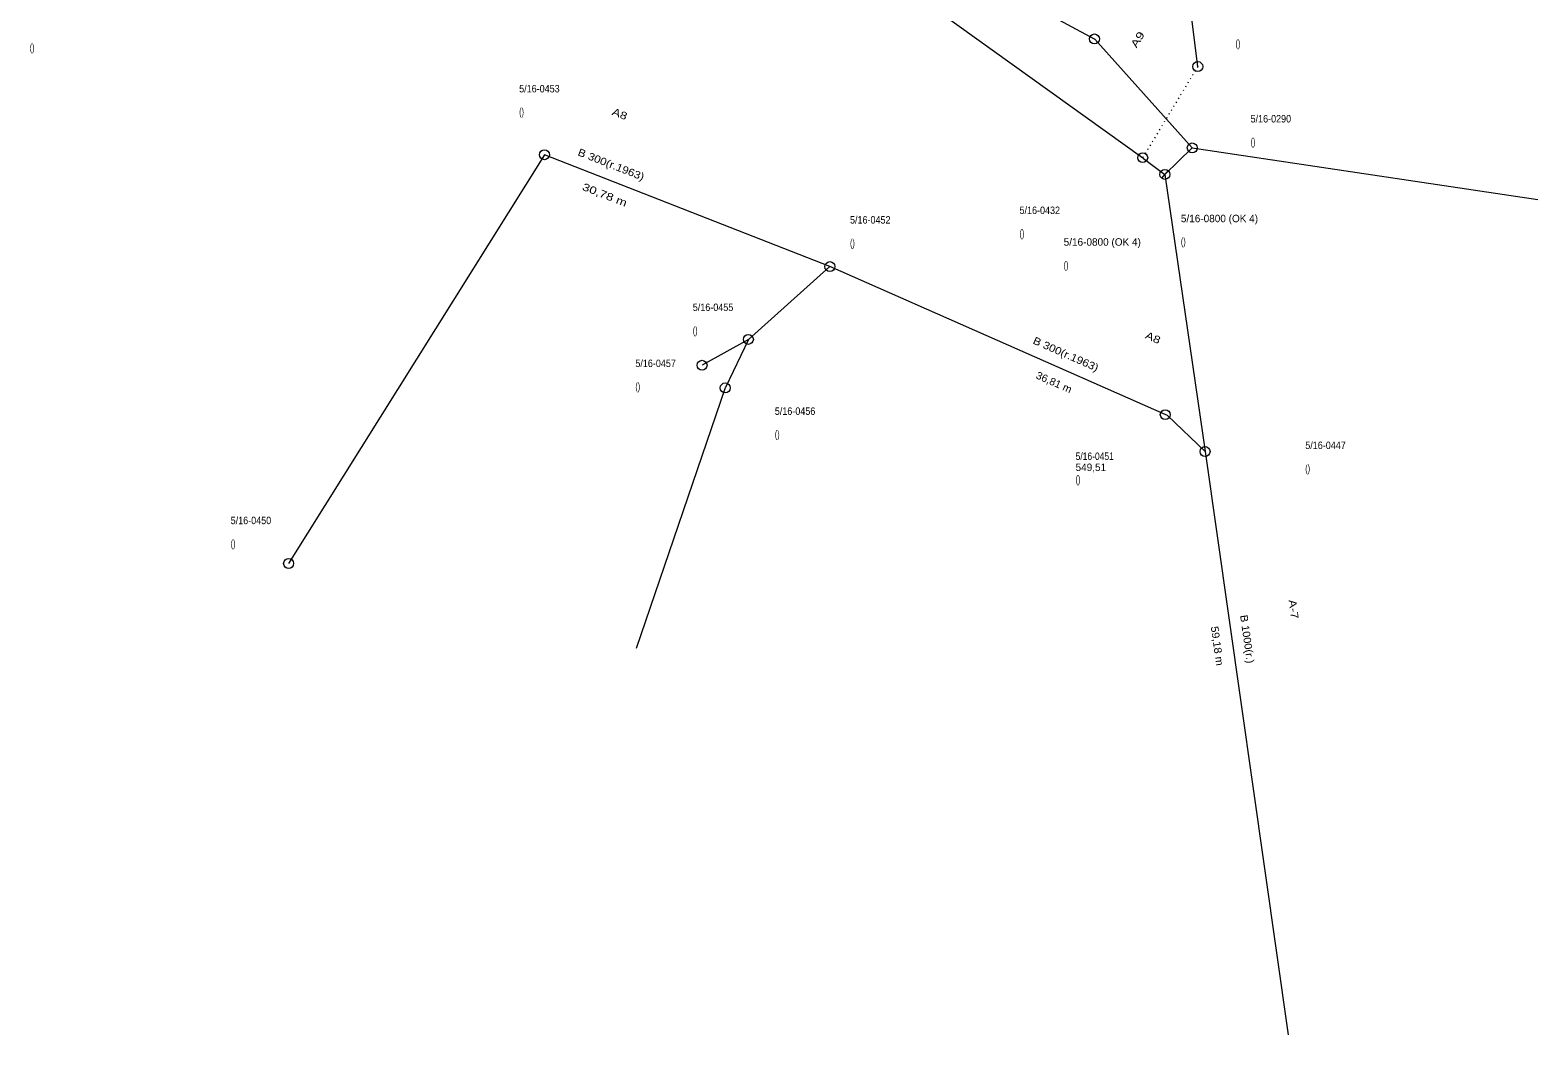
# Model space of a CAD drawing. Extents: x -710854 to -709799, y -1117012 to -1115891.
# Drawn here: x -710379.5 to -710228.1, y -1116702.7 to -1116601.8 of the extents above; entities that cross this region are included whole.
import ezdxf
from ezdxf.enums import TextEntityAlignment as Align

# ---------------------------------------------------------------- set-up
doc = ezdxf.new("R2010")
doc.units = 0
doc.header["$LTSCALE"] = 0.3
doc.linetypes.add('DOTTED', pattern=[1.5, 0.3, -1.2])
for name, color, linetype, lineweight in [('35', 7, 'Continuous', 25), ('36', 7, 'Continuous', 13), ('38', 7, 'Continuous', 13), ('44', 7, 'Continuous', 13)]:
    doc.layers.add(name, color=color, linetype=linetype, lineweight=lineweight)
doc.layers.add('48', color=7, linetype='Continuous')

msp = doc.modelspace()

# ---------------------------------------------------------------- linework, layer by layer
at = {"layer": '35', "lineweight": 13}
msp.add_line((-710262.82, -1116613.59), (-710265.57, -1116616.25), dxfattribs=at)
at = {"layer": '36'}
for points in [[(-710299.622, -1116588.059), (-710299.384, -1116588.249), (-710272.66, -1116602.62), (-710272.639, -1116602.644)], [(-710272.639, -1116602.644), (-710272.614, -1116602.671), (-710262.82, -1116613.59), (-710228.13, -1116618.78)]]:
    msp.add_lwpolyline(points, dxfattribs=at)
at = {"layer": '38'}
for p, q in [((-710262.27, -1116605.42), (-710268.259, -1116557.114)), ((-710339.8, -1116562.9), (-710267.796, -1116614.57)), ((-710299.2, -1116625.51), (-710327.851, -1116614.272)), ((-710307.38, -1116632.82), (-710312.03, -1116635.42)), ((-710309.701, -1116637.692), (-710318.65, -1116663.86))]:
    msp.add_line(p, q, dxfattribs=at)
at = {"layer": '38', "linetype": 'DOTTED'}
msp.add_line((-710262.27, -1116605.42), (-710267.796, -1116614.57), dxfattribs=at)
at = {"layer": '38'}
for points in [[(-710327.851, -1116614.272), (-710327.858, -1116614.269), (-710353.53, -1116655.33)], [(-710267.796, -1116614.57), (-710267.74, -1116614.61), (-710267.701, -1116614.639), (-710265.57, -1116616.25), (-710261.54, -1116644.09), (-710253.195, -1116702.676)], [(-710261.54, -1116644.09), (-710265.312, -1116640.479), (-710265.531, -1116640.382), (-710299.2, -1116625.51), (-710307.38, -1116632.82)], [(-710307.38, -1116632.82), (-710309.681, -1116637.641), (-710309.69, -1116637.66), (-710309.701, -1116637.692)]]:
    msp.add_lwpolyline(points, dxfattribs=at)
at = {"layer": '44'}
msp.add_line((-710265.252, -1116615.867), (-710265.904, -1116616.616), dxfattribs=at)
for centre in [(-710272.639, -1116602.644), (-710262.27, -1116605.42), (-710327.851, -1116614.272), (-710267.796, -1116614.57), (-710262.82, -1116613.59), (-710265.57, -1116616.25), (-710299.2, -1116625.51), (-710307.38, -1116632.82), (-710312.03, -1116635.42), (-710309.701, -1116637.692), (-710265.531, -1116640.382), (-710261.54, -1116644.09), (-710353.53, -1116655.33)]:
    msp.add_circle(centre, 0.5, dxfattribs=at)

# ---------------------------------------------------------------- texts
at = {"layer": '48'}
for s, rotation, width, p in [('A9', 58.87, 1.35, (-710267.9867, -1116602.8949)), ('A8', 338.58, 1.25, (-710320.4295, -1116610.523)), ('B 300(r.1963)', 338.58, 1.15, (-710321.29, -1116615.5987)), ('30,78 m', 338.58, 1.3, (-710321.9265, -1116618.647)), ('B 300(r.1963)', 336.17, 1.15, (-710275.661, -1116634.6391)), ('A8', 336.17, 1.25, (-710266.9135, -1116632.9931)), ('36,81 m', 336.17, 1.05, (-710276.851, -1116637.4703)), ('A-7', 278.11, 1.25, (-710253.0135, -1116659.9786)), ('B 1000(r.)', 278.11, 1.1, (-710257.677, -1116662.9761)), ('59,18 m', 278.11, 1.1, (-710260.6815, -1116663.6606))]:
    msp.add_text(s, height=0.75, rotation=rotation, dxfattribs=dict(at, width=width)).set_placement(p, align=Align.CENTER)
for s, width, p in [('()', 0.7, (-710379.52, -1116603.874)), ('()', 0.7, (-710258.475, -1116603.463)), ('5/16-0453', 0.9, (-710330.388, -1116608.015)), ('()', 0.7, (-710330.388, -1116610.325)), ('5/16-0290', 0.9, (-710256.965, -1116611.034)), ('()', 0.7, (-710256.965, -1116613.344)), ('5/16-0452', 0.9, (-710297.176, -1116621.19)), ('5/16-0432', 0.9, (-710280.159, -1116620.229)), ('()', 0.7, (-710280.159, -1116622.539)), ('()', 0.7, (-710297.176, -1116623.5)), ('()', 0.7, (-710263.964, -1116623.362)), ('()', 0.7, (-710275.729, -1116625.722)), ('5/16-0455', 0.9, (-710312.959, -1116629.973)), ('()', 0.7, (-710312.959, -1116632.283)), ('5/16-0457', 0.9, (-710318.723, -1116635.6)), ('()', 0.7, (-710318.723, -1116637.91)), ('5/16-0456', 0.9, (-710304.725, -1116640.403)), ('()', 0.7, (-710304.725, -1116642.713)), ('5/16-0447', 0.9, (-710251.476, -1116643.834)), ('5/16-0451', 0.85, (-710274.532, -1116644.932)), ('()', 0.7, (-710251.476, -1116646.144)), ('()', 0.7, (-710274.532, -1116647.242)), ('5/16-0450', 0.9, (-710359.346, -1116651.382)), ('()', 0.7, (-710359.346, -1116653.692))]:
    msp.add_text(s, height=0.75, dxfattribs=dict(at, width=width)).set_placement(p)
for s, p in [('5/16-0800 (OK 4)', (-710263.964, -1116621.052)), ('5/16-0800 (OK 4)', (-710275.729, -1116623.412)), ('549,51 ', (-710274.532, -1116646.042))]:
    msp.add_text(s, height=0.75, dxfattribs=at).set_placement(p)

doc.saveas('drawing.dxf')
